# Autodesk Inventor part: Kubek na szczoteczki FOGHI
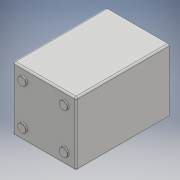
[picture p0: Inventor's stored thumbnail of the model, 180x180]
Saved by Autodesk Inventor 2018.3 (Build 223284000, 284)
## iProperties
Created: 2021-05
Part Number: Kubek na szczoteczki FOGHI
Material: Ogólny
Document SubType Name: Modeling
Designer: Verical
Density: 1 g/cm^3
Appearance: Domyślna
Author: Verical
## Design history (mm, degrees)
derived "Kubek prototyp.iam"
node "Bryła1"
node "Puszka.ipt:1"
node "nóżka.ipt:1"
node "nóżka.ipt:2"
node "nóżka.ipt:3"
node "nóżka.ipt:4"
node "Uchwyt US1.ipt:1"
